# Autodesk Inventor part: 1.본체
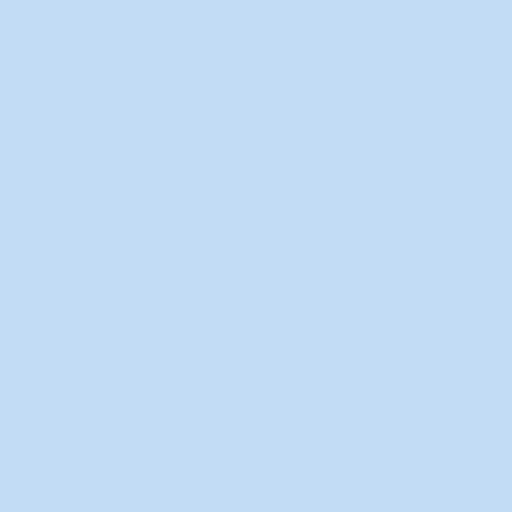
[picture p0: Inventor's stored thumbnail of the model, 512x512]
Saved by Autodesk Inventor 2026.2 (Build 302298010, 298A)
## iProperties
Created: 2026-09
Part Number: 1.본체
Material: 일반
Document SubType Name: Modeling
Designer: PC-2-06
Density: 1 g/cm^3
Appearance: 기본값
Author: PC-2-06
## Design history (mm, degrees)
